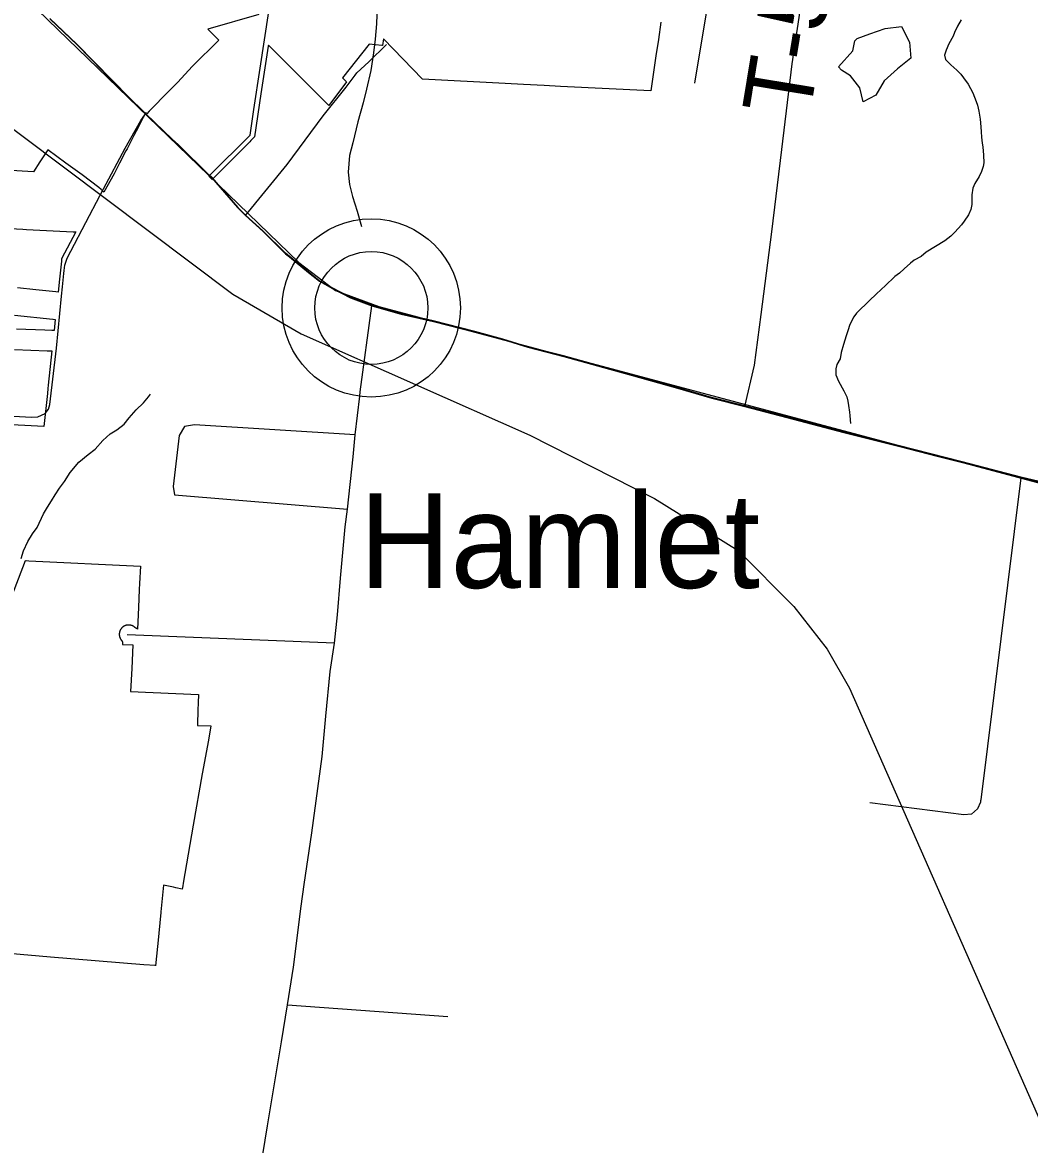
# Model space of a CAD drawing. Extents: x 0 to 39.3, y -3.9 to 22.
# Drawn here: x 4.794 to 5.634, y 17.092 to 18.028 of the extents above; entities that cross this region are included whole.
import ezdxf

# ---------------------------------------------------------------- set-up
doc = ezdxf.new("R2010")
doc.units = 0
for name, color, linetype in [('GM_X_Corporation', 7, 'Continuous'), ('GM_X_Minor_Lake', 7, 'Continuous'), ('GM_X_Minor_River', 7, 'Continuous'), ('GM_X_Rail_Line', 7, 'Continuous'), ('GM_X_State_Route', 7, 'Continuous'), ('GM_X_Township_Road', 7, 'Continuous'), ('GM_X_Township_Road_Text', 7, 'Continuous'), ('GM_X_Unincorporated', 7, 'Continuous'), ('GM_X_Unincorporated_Location', 7, 'Continuous'), ('GM_X_Unincorporated_Text', 7, 'Continuous')]:
    doc.layers.add(name, color=color, linetype=linetype)

msp = doc.modelspace()

# ---------------------------------------------------------------- linework, layer by layer
at = {"layer": 'GM_X_Corporation'}
for points in [[(4.99087, 18.03504), (4.9484, 18.02292), (4.95756, 18.0137), (4.93567, 17.99182), (4.92299, 17.9784), (4.91172, 17.96691), (4.91138, 17.96656), (4.90422, 17.95925), (4.89941, 17.95433), (4.89741, 17.95229), (4.89648, 17.95325), (4.89511, 17.95058), (4.89427, 17.94895), (4.89394, 17.9483), (4.89205, 17.94463), (4.89037, 17.94136), (4.88659, 17.93402), (4.88657, 17.93397), (4.88095, 17.92305), (4.87998, 17.92117), (4.87467, 17.91084), (4.87021, 17.90217), (4.86159, 17.88685), (4.85944, 17.88912), (4.85739, 17.89079), (4.84339, 17.90128), (4.82974, 17.911), (4.81474, 17.92219), (4.80816, 17.91206), (4.80272, 17.90368), (4.7605, 17.90623)], [(5.32648, 18.02866), (5.32442, 18.01434), (5.32243, 18.00051), (5.31824, 17.97135), (5.24265, 17.975), (5.2292, 17.97571), (5.21184, 17.97664), (5.19649, 17.97745), (5.12746, 17.98112), (5.09495, 18.01483), (5.09428, 18.00916), (5.09358, 18.00923), (5.08315, 18.01025), (5.06073, 17.98215), (5.06408, 17.97891), (5.04925, 17.95922), (5.0467, 17.96178), (4.99892, 18.00959), (4.99891, 18.00955), (4.99879, 18.00878), (4.99268, 17.96878), (4.9872, 17.9329), (4.98716, 17.93262), (4.98433, 17.9298), (4.98346, 17.92892), (4.95197, 17.89745), (4.94929, 17.90013), (4.94985, 17.90069), (4.9836, 17.93442), (4.98687, 17.95582), (4.99212, 17.99014), (4.99935, 18.03746)], [(4.81644, 18.03184), (4.83895, 18.0103), (4.88286, 17.96546), (4.89436, 17.95441), (4.89675, 17.95212), (4.91136, 17.93808), (4.91868, 17.93105), (4.92379, 17.92614), (4.94952, 17.90102), (4.95169, 17.8989), (4.97347, 17.87402), (4.97971, 17.86768), (4.99424, 17.85454), (5.01307, 17.83585), (5.03204, 17.82029), (5.04137, 17.81286), (5.05227, 17.80691), (5.06729, 17.79898), (5.0851, 17.79247), (5.10939, 17.78544), (5.13641, 17.77937), (5.17126, 17.77041), (5.1946, 17.76418), (5.21523, 17.75778), (5.24528, 17.75011), (5.30139, 17.73444), (5.34024, 17.72357), (5.36869, 17.71526), (5.39638, 17.70831), (5.42514, 17.7009), (5.47894, 17.68671), (5.52575, 17.67489), (5.57812, 17.66153), (5.62682, 17.64888), (5.65992, 17.64097)], [(5.65992, 17.64097), (5.62682, 17.64888), (5.57812, 17.66153), (5.52575, 17.67489), (5.47894, 17.68671), (5.42514, 17.7009), (5.39638, 17.70831), (5.36869, 17.71526), (5.34024, 17.72357), (5.30139, 17.73444), (5.24528, 17.75011), (5.21523, 17.75778), (5.1946, 17.76418), (5.17126, 17.77041), (5.13641, 17.77937), (5.10939, 17.78544), (5.0851, 17.79247), (5.06729, 17.79898), (5.05227, 17.80691), (5.04137, 17.81286), (5.03204, 17.82029), (5.01307, 17.83585), (4.99424, 17.85454), (4.97971, 17.86768), (4.97347, 17.87402), (4.95169, 17.8989), (4.94952, 17.90102), (4.92379, 17.92614), (4.91868, 17.93105), (4.91136, 17.93808), (4.89675, 17.95212), (4.89436, 17.95441), (4.88286, 17.96546), (4.83895, 18.0103), (4.81644, 18.03184)], [(4.75063, 17.85804), (4.79396, 17.85588), (4.79398, 17.85588), (4.79692, 17.85573), (4.79694, 17.85573), (4.83604, 17.85378), (4.83606, 17.85378), (4.83812, 17.85368), (4.82635, 17.83118), (4.82613, 17.8291), (4.82455, 17.81415), (4.82341, 17.80336), (4.82155, 17.80356), (4.80475, 17.80533), (4.78951, 17.80694)], [(4.7871, 17.78415), (4.81912, 17.78077), (4.81914, 17.78077), (4.821, 17.78057), (4.82001, 17.77118), (4.81813, 17.77124), (4.81812, 17.77124), (4.81235, 17.77145), (4.81233, 17.77145), (4.81227, 17.77145), (4.81225, 17.77145), (4.78879, 17.77228)], [(4.787, 17.75533), (4.8144, 17.75436), (4.81441, 17.75436), (4.81443, 17.75436), (4.81445, 17.75436), (4.81447, 17.75436), (4.81449, 17.75436), (4.81822, 17.75423), (4.81519, 17.72559), (4.81491, 17.72289), (4.81447, 17.71871), (4.81155, 17.69113), (4.67794, 17.69801)], [(4.73506, 17.4198), (4.79606, 17.57925), (4.7966, 17.57922), (4.79895, 17.5791), (4.89208, 17.5745), (4.8914, 17.56019), (4.89116, 17.55518), (4.89045, 17.54018), (4.88958, 17.52208), (4.88952, 17.52211), (4.88947, 17.52214), (4.88947, 17.52214), (4.88939, 17.52218), (4.88936, 17.5222), (4.88932, 17.52221), (4.88924, 17.52225), (4.88921, 17.52227), (4.88917, 17.52229), (4.88909, 17.52234), (4.88906, 17.52236), (4.88902, 17.52238), (4.88895, 17.52242), (4.88891, 17.52244), (4.88887, 17.52246), (4.8888, 17.5225), (4.88876, 17.52252), (4.88873, 17.52255), (4.88865, 17.52259), (4.88862, 17.52261), (4.88858, 17.52264), (4.88851, 17.52268), (4.88847, 17.5227), (4.88844, 17.52273), (4.88837, 17.52277), (4.88833, 17.52279), (4.8883, 17.52282), (4.88823, 17.52286), (4.88819, 17.52289), (4.88816, 17.52291), (4.88809, 17.52296), (4.88805, 17.52298), (4.88802, 17.52301), (4.88795, 17.52306), (4.88791, 17.52308), (4.88788, 17.52311), (4.88781, 17.52316), (4.88777, 17.52318), (4.88774, 17.52321), (4.88771, 17.52323), (4.88767, 17.52326), (4.88764, 17.52328), (4.88761, 17.52331), (4.88754, 17.52336), (4.8875, 17.52339), (4.88747, 17.52341), (4.8874, 17.52347), (4.88737, 17.52349), (4.88734, 17.52352), (4.88727, 17.52357), (4.88724, 17.5236), (4.8871, 17.52372), (4.88699, 17.52381), (4.88688, 17.52389), (4.88677, 17.52397), (4.88666, 17.52405), (4.88655, 17.52412), (4.88644, 17.5242), (4.88632, 17.52427), (4.88621, 17.52434), (4.88609, 17.52441), (4.88597, 17.52448), (4.88585, 17.52454), (4.88573, 17.5246), (4.88561, 17.52466), (4.88549, 17.52472), (4.88536, 17.52477), (4.88524, 17.52483), (4.88511, 17.52488), (4.88498, 17.52493), (4.88486, 17.52498), (4.88473, 17.52502), (4.8846, 17.52506), (4.88447, 17.5251), (4.88434, 17.52514), (4.88421, 17.52518), (4.88408, 17.52521), (4.88395, 17.52524), (4.88381, 17.52527), (4.88368, 17.5253), (4.88355, 17.52532), (4.88341, 17.52534), (4.88328, 17.52536), (4.88314, 17.52538), (4.88301, 17.52539), (4.88287, 17.52541), (4.88274, 17.52542), (4.8826, 17.52542), (4.88256, 17.52543), (4.88255, 17.52543), (4.88247, 17.52543), (4.88245, 17.52543), (4.88242, 17.52543), (4.88241, 17.52543), (4.88233, 17.52543), (4.88231, 17.52543), (4.88229, 17.52543), (4.88227, 17.52543), (4.88219, 17.52543), (4.88218, 17.52543), (4.88215, 17.52543), (4.88213, 17.52543), (4.88206, 17.52543), (4.88204, 17.52543), (4.88201, 17.52543), (4.88192, 17.52543), (4.88191, 17.52543), (4.88188, 17.52542), (4.88179, 17.52542), (4.88177, 17.52542), (4.88165, 17.52541), (4.88164, 17.52541), (4.88152, 17.5254), (4.8815, 17.5254), (4.88138, 17.52539), (4.88137, 17.52538), (4.88125, 17.52537), (4.88111, 17.52535), (4.88098, 17.52533), (4.88084, 17.52531), (4.88071, 17.52528), (4.88058, 17.52526), (4.88045, 17.52523), (4.88031, 17.52519), (4.88018, 17.52516), (4.88005, 17.52512), (4.88001, 17.52511), (4.87992, 17.52508), (4.87985, 17.52506), (4.87979, 17.52504), (4.87966, 17.525), (4.87964, 17.52499), (4.87954, 17.52495), (4.8795, 17.52494), (4.87947, 17.52493), (4.87941, 17.52491), (4.87928, 17.52485), (4.87916, 17.5248), (4.87903, 17.52475), (4.87891, 17.52469), (4.87879, 17.52463), (4.87867, 17.52457), (4.87855, 17.52451), (4.87843, 17.52444), (4.87831, 17.52437), (4.87819, 17.52431), (4.87808, 17.52423), (4.87796, 17.52416), (4.87785, 17.52409), (4.87781, 17.52406), (4.87774, 17.52401), (4.87763, 17.52393), (4.87752, 17.52385), (4.87741, 17.52376), (4.87731, 17.52368), (4.8772, 17.52359), (4.8771, 17.52351), (4.877, 17.52341), (4.8769, 17.52332), (4.8768, 17.52323), (4.8767, 17.52313), (4.87661, 17.52304), (4.87652, 17.52294), (4.87642, 17.52284), (4.87633, 17.52274), (4.87625, 17.52263), (4.87616, 17.52253), (4.87608, 17.52242), (4.87599, 17.52231), (4.87591, 17.5222), (4.87584, 17.52209), (4.87576, 17.52198), (4.87568, 17.52187), (4.87561, 17.52175), (4.87554, 17.52164), (4.87547, 17.52152), (4.87541, 17.5214), (4.87534, 17.52128), (4.87528, 17.52116), (4.87522, 17.52104), (4.87516, 17.52092), (4.87511, 17.52079), (4.87505, 17.52067), (4.875, 17.52054), (4.87495, 17.52042), (4.8749, 17.52029), (4.87486, 17.52016), (4.87482, 17.52003), (4.87478, 17.5199), (4.87474, 17.51977), (4.8747, 17.51964), (4.87467, 17.51951), (4.87464, 17.51938), (4.87461, 17.51924), (4.87458, 17.51911), (4.87456, 17.51898), (4.87453, 17.51884), (4.87452, 17.51871), (4.8745, 17.51857), (4.87448, 17.51844), (4.87447, 17.5183), (4.87446, 17.51817), (4.87445, 17.51803), (4.87445, 17.5179), (4.87444, 17.51776), (4.87444, 17.51763), (4.87444, 17.51749), (4.87445, 17.51735), (4.87445, 17.51722), (4.87446, 17.51708), (4.87447, 17.51695), (4.87449, 17.51681), (4.8745, 17.51668), (4.87452, 17.51654), (4.87454, 17.51641), (4.87457, 17.51628), (4.87459, 17.51614), (4.87462, 17.51601), (4.87465, 17.51588), (4.87468, 17.51575), (4.87471, 17.51561), (4.87475, 17.51548), (4.87479, 17.51535), (4.87483, 17.51522), (4.87487, 17.51509), (4.87492, 17.51497), (4.87497, 17.51484), (4.87502, 17.51471), (4.87507, 17.51459), (4.87512, 17.51446), (4.87518, 17.51434), (4.87524, 17.51422), (4.8753, 17.5141), (4.87536, 17.51398), (4.87543, 17.51386), (4.87549, 17.51374), (4.87556, 17.51362), (4.87564, 17.51351), (4.87571, 17.51339), (4.87578, 17.51328), (4.87586, 17.51317), (4.87594, 17.51306), (4.87602, 17.51295), (4.8761, 17.51284), (4.87619, 17.51274), (4.87627, 17.51263), (4.87636, 17.51253), (4.8764, 17.51247), (4.87644, 17.51242), (4.87648, 17.51237), (4.87652, 17.51231), (4.87655, 17.51226), (4.87659, 17.51221), (4.87662, 17.51215), (4.87665, 17.51209), (4.87669, 17.51204), (4.87672, 17.51198), (4.87675, 17.51192), (4.87678, 17.51186), (4.8768, 17.5118), (4.87683, 17.51174), (4.87685, 17.5117), (4.87686, 17.51169), (4.87686, 17.51168), (4.87688, 17.51162), (4.87691, 17.51156), (4.87693, 17.5115), (4.87695, 17.51144), (4.87697, 17.51138), (4.87699, 17.51132), (4.87701, 17.51125), (4.87703, 17.51119), (4.87705, 17.51113), (4.87706, 17.51106), (4.87708, 17.511), (4.87709, 17.51094), (4.8771, 17.51087), (4.87711, 17.51081), (4.87712, 17.51074), (4.87713, 17.51068), (4.87714, 17.51061), (4.87714, 17.51055), (4.87715, 17.51048), (4.87715, 17.51042), (4.87716, 17.51035), (4.87716, 17.51029), (4.87716, 17.51022), (4.87716, 17.51016), (4.87716, 17.51009), (4.87716, 17.51002), (4.87715, 17.50996), (4.87715, 17.50989), (4.87714, 17.50983), (4.87713, 17.50976), (4.87713, 17.5097), (4.87712, 17.50963), (4.87711, 17.50957), (4.87709, 17.50951), (4.87708, 17.50944), (4.87707, 17.50938), (4.87705, 17.50931), (4.87704, 17.50925), (4.87702, 17.50919), (4.88581, 17.50878), (4.88481, 17.48915), (4.88384, 17.4699), (4.94054, 17.46746), (4.94031, 17.46055), (4.94011, 17.45445), (4.93997, 17.45024), (4.93985, 17.44661), (4.93969, 17.44156), (4.95095, 17.44113), (4.94879, 17.42943), (4.94362, 17.40126), (4.93621, 17.35835), (4.92785, 17.30996), (4.92745, 17.30765), (4.92698, 17.30497), (4.92692, 17.30499), (4.92163, 17.30607), (4.91981, 17.30644), (4.91133, 17.30817), (4.90918, 17.28607), (4.90911, 17.28533), (4.90661, 17.25951), (4.90637, 17.25705), (4.90481, 17.24104), (4.90475, 17.24105), (4.89504, 17.24184), (4.81698, 17.24826), (4.78234, 17.25111)]]:
    msp.add_lwpolyline(points, dxfattribs=at)
at = {"layer": 'GM_X_Minor_Lake'}
for points in [[(5.50102, 18.01906), (5.51364, 18.02341), (5.52736, 18.02507), (5.53398, 18.01203), (5.53527, 17.9987), (5.52409, 17.98977), (5.5129, 17.9797), (5.50585, 17.96766), (5.49548, 17.96214), (5.49265, 17.97397), (5.48483, 17.98399)], [(5.48483, 17.98399), (5.47731, 17.98868), (5.47469, 17.99139), (5.48671, 18.00486), (5.48837, 18.0132), (5.49031, 18.01507), (5.50102, 18.01906)]]:
    msp.add_lwpolyline(points, dxfattribs=at)
at = {"layer": 'GM_X_Minor_River'}
for points in [[(5.08964, 18.04254), (5.08901, 18.02735), (5.08802, 18.01444), (5.08669, 18.00306), (5.08454, 17.98827), (5.08085, 17.97275), (5.07799, 17.96139), (5.07354, 17.9455), (5.06944, 17.92808), (5.0666, 17.91749), (5.0656, 17.90344), (5.06656, 17.89316), (5.06905, 17.88323), (5.07303, 17.871), (5.07661, 17.85801)], [(5.57715, 18.03063), (5.57402, 18.02536), (5.57165, 18.02008), (5.57046, 18.01706), (5.56693, 18.01065), (5.56456, 18.00537), (5.56335, 18.00121), (5.56405, 17.99739), (5.56854, 17.99313), (5.5734, 17.98848), (5.57677, 17.98537), (5.579, 17.98229), (5.58309, 17.9769), (5.58493, 17.97344), (5.58677, 17.9696), (5.58823, 17.96615), (5.58969, 17.96232), (5.59078, 17.95926), (5.59183, 17.9543), (5.59287, 17.94781), (5.59352, 17.94134), (5.59383, 17.93715), (5.59413, 17.93258), (5.5948, 17.92762), (5.59513, 17.92457), (5.59578, 17.91771), (5.59605, 17.91124), (5.59562, 17.9082), (5.59403, 17.90405), (5.59206, 17.8999), (5.58853, 17.89387), (5.58695, 17.8901), (5.58609, 17.88441), (5.58596, 17.87642), (5.58513, 17.87225), (5.58315, 17.86772), (5.57964, 17.86246), (5.57731, 17.85946), (5.57189, 17.85347), (5.56841, 17.8501), (5.5634, 17.84601), (5.54804, 17.83677), (5.54379, 17.83304), (5.53804, 17.8301), (5.53495, 17.82749), (5.52955, 17.82264), (5.52569, 17.81928), (5.52184, 17.81631), (5.51372, 17.80846), (5.51064, 17.80585), (5.506, 17.80137), (5.50098, 17.79651), (5.48977, 17.78568), (5.48744, 17.78268), (5.48429, 17.77626), (5.48268, 17.77097), (5.48109, 17.76681), (5.47907, 17.75962), (5.47705, 17.75281), (5.4762, 17.7475), (5.47346, 17.74298), (5.47264, 17.73919), (5.47255, 17.73425), (5.47475, 17.72888), (5.47917, 17.72082), (5.48175, 17.71583), (5.48245, 17.71239), (5.48315, 17.70858), (5.48382, 17.70324), (5.48415, 17.70019)], [(4.84846, 17.66778), (4.85423, 17.67225), (4.86079, 17.67936), (4.86694, 17.68497), (4.87231, 17.68831), (4.87846, 17.69315), (4.88271, 17.69841), (4.88851, 17.70516), (4.89467, 17.71076), (4.89892, 17.71601), (4.90048, 17.71827)], [(5.48415, 17.70019), (5.48447, 17.69676), (5.4848, 17.69371)], [(4.79252, 17.58089), (4.79451, 17.58731), (4.79804, 17.59523), (4.80193, 17.60163), (4.8058, 17.60689), (4.81129, 17.6182), (4.81441, 17.62385), (4.8179, 17.62911), (4.82101, 17.63401), (4.82451, 17.63965), (4.82877, 17.64528), (4.83343, 17.65281), (4.84077, 17.66143), (4.84846, 17.66778)]]:
    msp.add_lwpolyline(points, dxfattribs=at)
at = {"layer": 'GM_X_Rail_Line'}
for points in [[(4.18622, 18.62831), (4.16229, 18.58605), (4.13124, 18.5367), (4.12369, 18.48529), (4.12892, 18.43918), (4.15569, 18.40598), (4.19759, 18.37648), (4.47535, 18.17304), (4.96919, 17.80149), (5.02614, 17.76837), (5.21709, 17.68386), (5.32106, 17.63105), (5.39089, 17.58757), (5.43744, 17.54098), (5.46537, 17.50526), (5.48399, 17.47265), (5.64071, 17.11701), (5.6795, 17.02694), (5.72761, 16.96171), (5.77261, 16.91201), (5.96967, 16.67439), (6.19906, 16.40813)], [(4.18622, 18.62831), (4.5461, 18.29048), (5.02431, 17.8281), (5.05481, 17.80455), (5.09109, 17.79139), (5.82191, 17.59599), (5.89111, 17.57346), (5.98316, 17.53226), (6.18094, 17.42458)]]:
    msp.add_lwpolyline(points, dxfattribs=at)
at = {"layer": 'GM_X_State_Route'}
msp.add_line((5.0756, 17.72014), (5.08533, 17.79195), dxfattribs=at)
for points in [[(5.39661, 17.70778), (5.40454, 17.74242), (5.41021, 17.78467), (5.41899, 17.85362), (5.42754, 17.92239), (5.43621, 17.99379), (5.445, 18.05325), (5.44884, 18.08292), (5.45585, 18.13046), (5.45728, 18.14137), (5.4643, 18.19014), (5.47518, 18.26261), (5.48537, 18.33475), (5.4953, 18.39669), (5.50563, 18.46932), (5.5167, 18.54341), (5.52615, 18.6076), (5.53853, 18.69319), (5.54726, 18.75446), (5.55381, 18.80293), (5.55541, 18.8138)], [(4.81667, 18.03132), (4.83918, 18.00978), (4.88309, 17.96494), (4.89459, 17.95389)], [(4.89459, 17.95389), (4.89698, 17.9516), (4.9094, 17.93966)], [(4.9094, 17.93966), (4.91159, 17.93755), (4.91891, 17.93053), (4.92402, 17.92562), (4.94975, 17.9005), (4.95192, 17.89838), (4.9737, 17.8735), (4.97994, 17.86716), (4.99447, 17.85402), (5.0133, 17.83533), (5.01646, 17.83273)], [(5.01646, 17.83273), (5.03227, 17.81977), (5.0416, 17.81233), (5.0525, 17.80639), (5.06752, 17.79845), (5.08533, 17.79195)], [(5.08533, 17.79195), (5.10963, 17.78491), (5.13664, 17.77884), (5.1715, 17.76989), (5.19483, 17.76366), (5.21546, 17.75726), (5.24551, 17.74959), (5.30162, 17.73392), (5.34047, 17.72305), (5.36892, 17.71474), (5.39661, 17.70778)], [(5.02888, 17.30874), (5.03515, 17.35183), (5.0437, 17.41563), (5.04692, 17.44932), (5.05046, 17.48673), (5.05407, 17.51015), (5.05648, 17.53379), (5.05922, 17.56457), (5.06305, 17.60749), (5.06483, 17.62203), (5.0698, 17.66583), (5.07139, 17.6841), (5.07511, 17.71655), (5.0756, 17.72014)], [(5.39661, 17.70778), (5.42537, 17.70038), (5.42639, 17.70011)], [(5.42639, 17.70011), (5.47917, 17.68619), (5.52598, 17.67437), (5.5572, 17.66641)], [(5.5572, 17.66641), (5.57835, 17.66101), (5.62705, 17.64836), (5.66015, 17.64044), (5.7007, 17.62933), (5.737, 17.61834), (5.75295, 17.61373)], [(4.95275, 16.82373), (4.96401, 16.88809), (4.97427, 16.96421), (4.98635, 17.03558), (4.99806, 17.10732), (5.00975, 17.17754), (5.01473, 17.20839), (5.0198, 17.2398), (5.02626, 17.2907), (5.02888, 17.30874)]]:
    msp.add_lwpolyline(points, dxfattribs=at)
at = {"layer": 'GM_X_Township_Road'}
for p, q in [((5.62705, 17.64836), (5.5935, 17.37962)), ((4.92048, 17.63409), (5.06483, 17.62203)), ((5.05407, 17.51015), (4.88094, 17.51723)), ((5.01473, 17.20839), (5.14863, 17.19861))]:
    msp.add_line(p, q, dxfattribs=at)
for points in [[(5.35477, 17.97783), (5.38378, 18.15203), (5.4018, 18.27895)], [(5.07124, 17.98442), (5.07274, 17.9864), (5.08262, 17.99564), (5.09759, 18.00997)], [(4.97994, 17.86716), (5.01446, 17.90997), (5.04472, 17.95042), (5.06373, 17.97451), (5.07124, 17.98442)], [(4.7231, 17.70331), (4.80079, 17.69902), (4.8064, 17.69926), (4.81251, 17.70207), (4.81532, 17.70562), (4.81655, 17.70958), (4.82192, 17.75664), (4.82621, 17.80007), (4.82696, 17.80767), (4.82811, 17.81873), (4.82836, 17.82129), (4.8291, 17.82575), (4.83092, 17.83178), (4.84966, 17.86719), (4.86139, 17.88965), (4.8793, 17.92358), (4.89235, 17.9467), (4.89644, 17.95211)], [(5.07139, 17.6841), (4.93733, 17.69262), (4.92899, 17.69119), (4.92456, 17.68357), (4.91942, 17.64118), (4.92048, 17.63409)], [(5.5935, 17.37962), (5.59337, 17.37862), (5.59327, 17.37764), (5.59085, 17.37201), (5.58581, 17.36758), (5.57936, 17.36699), (5.50082, 17.37699)]]:
    msp.add_lwpolyline(points, dxfattribs=at)
at = {"layer": 'GM_X_Unincorporated'}
for radius in [0.0744, 0.04716]:
    msp.add_circle((5.08482, 17.79009), radius, dxfattribs=at)
at = {"layer": 'GM_X_Unincorporated_Location'}
msp.add_line((5.08482, 17.79009), (5.08482, 17.79009), dxfattribs=at)

# ---------------------------------------------------------------- texts
at = {"layer": 'GM_X_Township_Road_Text'}
msp.add_text('T-527', height=0.056818, rotation=80.67597, dxfattribs=at).set_placement((5.45038, 17.94791))
at = {"layer": 'GM_X_Unincorporated_Text'}
msp.add_text('Hamlet', height=0.078977, rotation=0.00001, dxfattribs=at).set_placement((5.07473, 17.55635))

doc.saveas('drawing.dxf')
